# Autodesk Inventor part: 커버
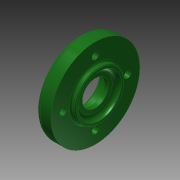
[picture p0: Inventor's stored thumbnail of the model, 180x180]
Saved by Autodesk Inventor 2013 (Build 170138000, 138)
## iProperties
Created: 2015-11
Part Number: 커버
Material: 알루미늄 6061
Document SubType Name: Modeling
Designer: mduedu
Density: 2.71 g/cm^3
Mass: 57.8273 g
Surface Area: 81.1807 cm^2
Volume: 21.3385 cm^3
Author: mduedu
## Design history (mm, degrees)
sketch "스케치1"
  geometry: L1 (-6.5, 0)-(6.5, 0); L2 (-6.5, 0)-(-6.5, 29); L3 (-6.5, 29)-(3.5, 29); L4 (3.5, 29)-(3.5, 16); L5 (3.5, 16)-(6.5, 16); L6 (6.5, 16)-(6.5, 0); 2 further points
  constraints: 12 end point, 3 perpendicular, 2 parallel, 1 coincident, 1 horizontal, 1 midpoint
  dimensions: "d0" = 13 distance of L1.start L1.end; "d1" = 58 diameter of L3 L1; "d2" = 3 distance of L4.end L5.end; "d3" = 32 diameter of L5 L1
revolve "회전1" sketch "스케치1" stored, may be unused: angle "d4" = 90 deg
hole "구멍1" diameter "d7" = 28; stored, may be unused: countersink angle "d11" = 90 deg, drill point angle "d13" = 0 deg; dims "d8" = 6, "d9" = 4, "d10" = 2, "d12" = 3, "d65" = 10, "d66" = 10
hole "구멍2" diameter "d16" = 25; stored, may be unused: countersink angle "d20" = 90 deg, drill point angle "d22" = 0 deg; dims "d17" = 6, "d18" = 4, "d19" = 2, "d21" = 7.3, "d67" = 10, "d68" = 10
hole "구멍3" diameter "d25" = 17; stored, may be unused: countersink angle "d29" = 90 deg, drill point angle "d31" = 0 deg; dims "d23" = 10, "d24" = 10, "d26" = 6, "d27" = 4, "d28" = 2, "d30" = 4.2
chamfer "모따기1" distance "d32" = 0.7; stored, may be unused: second distance "d33" = 2, angle "d34" = 30 deg
fillet "모깎기1" dims "d35" = 0.2
fillet "모깎기2" dims "d36" = 3
fillet "모깎기3" dims "d37" = 3
fillet "모깎기4" dims "d38" = 1
sketch "스케치3" dims "d61" = 42
  geometry: C1 r 29 at (0, 0) reference; 2 further points
  constraints: 2 vertical alignment, 1 coincident, 2 other
hole "구멍4" sketch "스케치3" at (0, -21) diameter "d44" = 4.5; stored, may be unused: countersink angle "d48" = 90 deg, drill point angle "d50" = 0 deg; dims "d45" = 6, "d46" = 8, "d47" = 4.6, "d49" = 8
chamfer "모따기2" distance "d62" = 0.5; stored, may be unused: second distance "d63" = 2, angle "d64" = 45 deg
node "솔리드1"
pattern_circular "원형 패턴1" dims angle "d54" = 360 deg
